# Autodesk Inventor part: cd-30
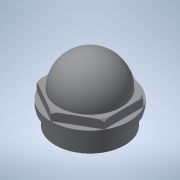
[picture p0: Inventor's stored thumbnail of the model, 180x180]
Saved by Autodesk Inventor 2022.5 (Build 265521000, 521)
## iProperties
Created: 2016-12
Part Number: cd-30
Material: 一般
Document SubType Name: Modeling
Designer: imaocorp
Density: 1 g/cm^3
Appearance: 既定
Author: imaocorp
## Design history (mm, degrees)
node "cd-30.x_t1"
node "cd-30"
node "Base1"
